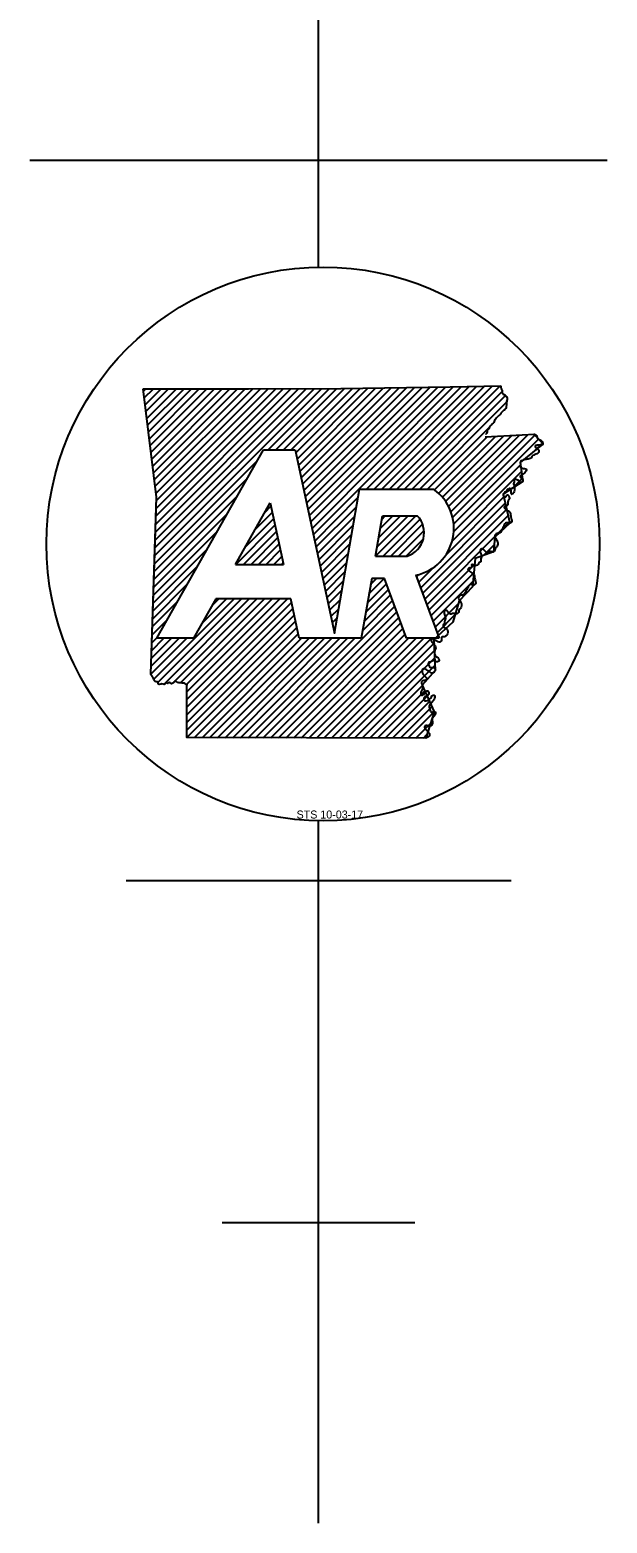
# Model space of a CAD drawing. Extents: x -13171 to 18763, y -8840 to 11152.
# Drawn here: x 5297 to 5823, y -4773 to -3413 of the extents above; entities that cross this region are included whole.
import ezdxf

# ---------------------------------------------------------------- set-up
doc = ezdxf.new("R2010")
doc.units = 0
doc.layers.add('Level 48', color=7, linetype='Continuous')

msp = doc.modelspace()

# ---------------------------------------------------------------- linework, layer by layer
at = {"layer": 'Level 48'}
for p, q in [((5560.1, -3629.5), (5560.1, -2053.7)), ((5296.9, -3532.1), (5823.2, -3532.1)), ((5545.6, -3827.2), (5633.5, -3739.3)), ((5546.8, -3833), (5640.5, -3739.2)), ((5548, -3838.7), (5647.6, -3739.1)), ((5549.2, -3844.4), (5654.7, -3739)), ((5550.5, -3850.2), (5661.8, -3738.9)), ((5551.7, -3855.9), (5668.8, -3738.8)), ((5552.9, -3861.6), (5675.9, -3738.7)), ((5554.2, -3867.4), (5683, -3738.5)), ((5555.4, -3873.1), (5690.1, -3738.4)), ((5603.8, -3831.7), (5697.3, -3738.2)), ((5610.7, -3831.7), (5704.4, -3738)), ((5617.7, -3831.7), (5711.5, -3737.9)), ((5624.7, -3831.7), (5718.7, -3737.7)), ((5631.6, -3831.7), (5725.8, -3737.5)), ((5400.5, -3742.4), (5402.7, -3740.3)), ((5401.3, -3748.6), (5409.6, -3740.3)), ((5402, -3754.8), (5416.6, -3740.3)), ((5402.8, -3761), (5423.5, -3740.3)), ((5403.6, -3767.2), (5430.5, -3740.3)), ((5404.3, -3773.4), (5437.5, -3740.3)), ((5405.1, -3779.6), (5444.4, -3740.3)), ((5405.9, -3785.8), (5451.4, -3740.3)), ((5406.7, -3792), (5458.3, -3740.3)), ((5407.4, -3798.2), (5465.3, -3740.3)), ((5408.2, -3804.4), (5472.3, -3740.3)), ((5409, -3810.6), (5479.2, -3740.3)), ((5409.7, -3816.8), (5486.2, -3740.3)), ((5410.5, -3823), (5493.2, -3740.3)), ((5410.7, -3892.4), (5562.9, -3740.2)), ((5411, -3885.2), (5556, -3740.2)), ((5411.2, -3878), (5549, -3740.2)), ((5411.3, -3829.1), (5500.1, -3740.3)), ((5411.5, -3870.8), (5542, -3740.2)), ((5411.7, -3863.6), (5535, -3740.2)), ((5411.9, -3856.4), (5528, -3740.2)), ((5412.1, -3835.3), (5507.1, -3740.3)), ((5412.2, -3849.2), (5521.1, -3740.3)), ((5412.4, -3841.9), (5514.1, -3740.3)), ((5514.2, -3795.9), (5569.9, -3740.2)), ((5521.1, -3795.9), (5576.9, -3740.1)), ((5528.1, -3795.9), (5583.9, -3740.1)), ((5535.1, -3795.9), (5591, -3740)), ((5539.4, -3798.5), (5598.1, -3739.9)), ((5540.6, -3804.3), (5605.2, -3739.8)), ((5541.9, -3810), (5612.2, -3739.6)), ((5543.1, -3815.7), (5619.3, -3739.5)), ((5544.3, -3821.5), (5626.4, -3739.4)), ((5638.6, -3831.7), (5727.4, -3742.9)), ((5645.6, -3831.7), (5730.7, -3746.5)), ((5652.5, -3831.7), (5731.6, -3752.6)), ((5659.5, -3831.7), (5715.7, -3775.5)), ((5665.8, -3832.3), (5714.3, -3783.8)), ((5669.6, -3835.5), (5721.7, -3783.4)), ((5673, -3839.1), (5729, -3783.1)), ((5676, -3843), (5736.4, -3782.7)), ((5678.6, -3847.4), (5743.7, -3782.3)), ((5680.8, -3852.2), (5751.1, -3781.9)), ((5682.4, -3857.6), (5757.7, -3782.3)), ((5683.3, -3863.6), (5760.9, -3786)), ((5757.8, -3796), (5764.2, -3789.7)), ((5410.5, -3899.6), (5504.5, -3805.6)), ((5412.8, -3967.5), (5510, -3795.9)), ((5510, -3795.9), (5538.9, -3795.9)), ((5681.9, -3879), (5745.1, -3815.7)), ((5683.3, -3870.5), (5744.3, -3809.6)), ((5410.3, -3906.8), (5495.4, -3821.6)), ((5597.5, -3831.7), (5664.9, -3831.7)), ((5737.3, -3830.5), (5745.9, -3821.9)), ((5410, -3914), (5486.3, -3837.7)), ((5484.3, -3900.2), (5516.1, -3844)), ((5511.1, -3852.8), (5516.7, -3847.1)), ((5556.6, -3878.9), (5596.1, -3839.3)), ((5557.8, -3884.6), (5594.7, -3847.8)), ((5653.1, -3921.7), (5730.3, -3844.4)), ((5675.8, -3892), (5729, -3838.8)), ((5409.8, -3921.2), (5477.2, -3853.8)), ((5492.9, -3884.9), (5519.2, -3858.6)), ((5502, -3868.8), (5518, -3852.9)), ((5559.1, -3890.3), (5593.2, -3856.2)), ((5612.2, -3892.6), (5648.8, -3855.9)), ((5613.6, -3884.2), (5641.8, -3855.9)), ((5615, -3875.7), (5634.9, -3855.9)), ((5616.5, -3867.3), (5627.9, -3855.9)), ((5618, -3858.9), (5620.9, -3855.9)), ((5618.5, -3855.9), (5650.2, -3855.9)), ((5619.1, -3892.6), (5652.7, -3859)), ((5655, -3926.7), (5731.6, -3850.1)), ((5656.9, -3931.8), (5733, -3855.8)), ((5658.8, -3936.9), (5734.3, -3861.4)), ((5409.5, -3928.4), (5468.1, -3869.8)), ((5484.6, -3900.2), (5520.4, -3864.4)), ((5491.6, -3900.2), (5521.7, -3870.1)), ((5560.3, -3896.1), (5591.7, -3864.6)), ((5561.5, -3901.8), (5590.3, -3873.1)), ((5626.1, -3892.6), (5655, -3863.6)), ((5633.1, -3892.6), (5656.3, -3869.3)), ((5409.3, -3935.6), (5459, -3885.9)), ((5498.6, -3900.2), (5522.9, -3875.8)), ((5505.5, -3900.2), (5524.1, -3881.6)), ((5512.5, -3900.2), (5525.3, -3887.3)), ((5562.7, -3907.5), (5588.8, -3881.5)), ((5640, -3892.6), (5655.7, -3876.9)), ((5710.4, -3892.2), (5720.2, -3882.4)), ((5409.1, -3942.8), (5449.9, -3901.9)), ((5484.3, -3900.2), (5528.1, -3900.2)), ((5519.5, -3900.2), (5526.6, -3893)), ((5526.4, -3900.2), (5527.8, -3898.8)), ((5564, -3913.3), (5587.3, -3889.9)), ((5565.2, -3919), (5585.8, -3898.4)), ((5612.1, -3892.6), (5641.1, -3892.6)), ((5660.6, -3942), (5702.4, -3900.2)), ((5566.4, -3924.8), (5584.4, -3906.8)), ((5567.7, -3930.5), (5582.9, -3915.3)), ((5606.1, -3926.9), (5620.1, -3912.9)), ((5607.6, -3918.4), (5613.1, -3912.9)), ((5620.3, -3912.9), (5608.6, -3912.9)), ((5640.4, -3967.5), (5620.3, -3912.9)), ((5648.8, -3910), (5670.1, -3967.5)), ((5649.4, -3911.5), (5651.5, -3909.4)), ((5651.2, -3916.6), (5664.5, -3903.3)), ((5662.5, -3947.1), (5701.6, -3908)), ((5664.4, -3952.2), (5700.9, -3915.7)), ((5408.8, -3950), (5440.8, -3918)), ((5568.9, -3936.2), (5581.4, -3923.7)), ((5601.7, -3952.2), (5625.8, -3928)), ((5603.2, -3943.7), (5624, -3923)), ((5604.7, -3935.3), (5622.1, -3917.9)), ((5408.6, -3957.2), (5431.7, -3934.1)), ((5409.9, -4004.7), (5483.1, -3931.5)), ((5414, -4007.5), (5490, -3931.5)), ((5419, -4009.5), (5497, -3931.5)), ((5427.3, -4008.2), (5504, -3931.5)), ((5434.4, -4008.1), (5510.9, -3931.5)), ((5439.8, -4009.6), (5517.9, -3931.5)), ((5440, -4016.3), (5524.9, -3931.5)), ((5440.1, -4023.3), (5531.8, -3931.5)), ((5440.1, -4030.2), (5535.5, -3934.8)), ((5440.1, -4037.2), (5536.7, -3940.5)), ((5466.5, -3931.5), (5446.2, -3967.5)), ((5454.1, -3953.6), (5476.1, -3931.5)), ((5463.1, -3937.5), (5469.1, -3931.5)), ((5534.8, -3931.5), (5466.5, -3931.5)), ((5509.8, -4058), (5629.6, -3938.2)), ((5516.7, -4058), (5631.5, -3943.3)), ((5570.1, -3942), (5580, -3932.1)), ((5571.3, -3947.7), (5578.5, -3940.6)), ((5600.3, -3960.6), (5627.7, -3933.1)), ((5666.3, -3957.3), (5687.6, -3935.9)), ((5408.4, -3964.4), (5422.7, -3950.1)), ((5440.1, -4044.1), (5538, -3946.3)), ((5440.1, -4051.1), (5539.2, -3952)), ((5523.7, -4058), (5633.4, -3948.4)), ((5530.7, -4058.1), (5635.2, -3953.5)), ((5572.6, -3953.5), (5577, -3949)), ((5668.2, -3962.4), (5684.7, -3945.9)), ((5407.3, -4000.3), (5440.1, -3967.5)), ((5407.4, -3993.2), (5433.1, -3967.5)), ((5407.6, -3986), (5426.2, -3967.5)), ((5407.9, -3978.8), (5419.2, -3967.5)), ((5408.1, -3971.6), (5413.6, -3966.2)), ((5446.2, -3967.5), (5412.8, -3967.5)), ((5440.2, -4057.9), (5540.4, -3957.7)), ((5447.2, -4057.9), (5541.6, -3963.5)), ((5454.2, -4057.9), (5544.6, -3967.5)), ((5461.1, -4057.9), (5551.6, -3967.5)), ((5468.1, -4058), (5558.5, -3967.5)), ((5475, -4058), (5565.5, -3967.5)), ((5482, -4058), (5572.4, -3967.5)), ((5488.9, -4058), (5579.4, -3967.5)), ((5495.9, -4058), (5586.4, -3967.5)), ((5502.8, -4058), (5593.3, -3967.5)), ((5537.6, -4058.1), (5637.1, -3958.6)), ((5599.1, -3967.5), (5542.5, -3967.5)), ((5544.6, -4058.1), (5639, -3963.7)), ((5551.5, -4058.1), (5642.1, -3967.5)), ((5558.5, -4058.1), (5649.1, -3967.5)), ((5565.4, -4058.1), (5656, -3967.5)), ((5572.4, -4058.1), (5663, -3967.5)), ((5573.8, -3959.2), (5575.6, -3957.4)), ((5670.1, -3967.5), (5640.4, -3967.5)), ((5579.3, -4058.1), (5665.3, -3972.1)), ((5586.3, -4058.1), (5665.6, -3978.8)), ((5593.2, -4058.2), (5666, -3985.4)), ((5600.2, -4058.2), (5666.3, -3992.1)), ((5607.2, -4058.2), (5654.8, -4010.5)), ((5614.1, -4058.2), (5657, -4015.3)), ((5621.1, -4058.2), (5659.1, -4020.1)), ((5628, -4058.2), (5661.3, -4025)), ((5635, -4058.2), (5663.4, -4029.8)), ((5641.9, -4058.2), (5665.2, -4034.9)), ((5648.9, -4058.3), (5662.1, -4045.1)), ((5655.8, -4058.3), (5658.9, -4055.2)), ((5560.1, -4773.2), (5560.1, -4133.6)), ((5384.7, -4188), (5735.6, -4188)), ((5472.4, -4499.6), (5647.8, -4499.6))]:
    msp.add_line(p, q, dxfattribs=at)
for points in [[(5400.2, -3740.3), (5496.3, -3740.3), (5580.7, -3740.1), (5680.1, -3738.6), (5726.2, -3737.5)], [(5400.2, -3740.3), (5496.3, -3740.3), (5580.6, -3740.1), (5680.1, -3738.6), (5726.2, -3737.5)], [(5410.8, -3889.7), (5412.5, -3839), (5400.2, -3740.3)], [(5407.2, -4000.3), (5412.5, -3839), (5400.2, -3740.3)], [(5756.4, -3781.7), (5764.8, -3790.4), (5744, -3807.4), (5746.3, -3824.6), (5728.5, -3836.3), (5734.6, -3862.8), (5720.9, -3875.3), (5719.6, -3888.9), (5703, -3894.9), (5700.4, -3920.5), (5688.4, -3933.4), (5682.6, -3952.7), (5665.2, -3968.6), (5666.5, -3996.8), (5654.6, -4010.1), (5665.4, -4034.3), (5658, -4058.3)], [(5712, -3783.9), (5757.1, -3781.6)], [(5712, -3783.9), (5757.1, -3781.6)], [(5538.9, -3795.9), (5574.6, -3962.9), (5597.5, -3831.7)], [(5516.1, -3844), (5528.1, -3900.2)], [(5612.1, -3892.6), (5618.5, -3855.9)], [(5407.2, -4000.3), (5410.8, -3889.7)], [(5608.6, -3912.9), (5599.1, -3967.5)], [(5542.5, -3967.5), (5534.8, -3931.5)], [(5658, -4058.3), (5440.1, -4057.9), (5440, -4009.8)], [(5657.9, -4058.3), (5440.1, -4057.9), (5440.1, -4009.8)]]:
    msp.add_lwpolyline(points, dxfattribs=at)
msp.add_ellipse((5564.2, -3881.6), major_axis=(252.1, 0), ratio=0.999976, dxfattribs=at)
for centre, major_axis, start_param, end_param in [((5639.9, -3867.4), (-43.6, 0), 1.777838, 4.099264), ((5634.1, -3871.4), (-22.3, 0), 1.887169, 3.90762)]:
    msp.add_ellipse(centre, major_axis=major_axis, ratio=0.999987, start_param=start_param, end_param=end_param, dxfattribs=at)
for points in [[(5726.2, -3737.5), (5726.5, -3740.1), (5727.3, -3741.5), (5727.5, -3744), (5728.5, -3745.1), (5730.3, -3746.2), (5731.7, -3747.8), (5732.1, -3749.9), (5731.6, -3751.9), (5731.5, -3754.3), (5731.3, -3756.3), (5730.9, -3758.1), (5729.5, -3759.6), (5728.2, -3760.7), (5726.9, -3761.9), (5726, -3763.3), (5724.5, -3764.7), (5722.9, -3766.2), (5721.6, -3767.5), (5720.4, -3769.1), (5719.8, -3771), (5718.5, -3772.3), (5717.4, -3773.5), (5716, -3775.1), (5715.3, -3776.7), (5713.9, -3778.5), (5713.6, -3780.3), (5712.7, -3781.7), (5712.6, -3782)], [(5726.2, -3737.5), (5726.5, -3740.1), (5727.4, -3741.5), (5727.5, -3744), (5728.5, -3745.1), (5730.2, -3746.1), (5731.8, -3747.9), (5732.1, -3749.9), (5731.7, -3752), (5731.5, -3754.3), (5731.3, -3756.3), (5730.9, -3758.1), (5729.5, -3759.6), (5728.1, -3760.7), (5726.9, -3761.9), (5726, -3763.3), (5724.5, -3764.7), (5722.9, -3766.2), (5721.7, -3767.5), (5720.4, -3769.1), (5719.8, -3771), (5718.5, -3772.3), (5717.4, -3773.5), (5716, -3775.1), (5715.3, -3776.7), (5713.9, -3778.5), (5713.6, -3780.3), (5712.7, -3781.7), (5712.6, -3782)], [(5756.4, -3781.7), (5757.1, -3781.6), (5759.1, -3783.7), (5760, -3785.6), (5761.3, -3786.5), (5762.8, -3787.1), (5763.9, -3788.4), (5764.7, -3790), (5764.3, -3791.3), (5762.6, -3791.4), (5760.8, -3791.7), (5759, -3791.6), (5757.5, -3792.8), (5758.9, -3794.4), (5760.6, -3795.9), (5761.1, -3797.5), (5760.1, -3799), (5758.2, -3799.9), (5756.4, -3800.6), (5754.7, -3802), (5753.9, -3803.4), (5752.1, -3804), (5750.2, -3804.5), (5748.5, -3804.7), (5746.6, -3805.1), (5744.8, -3806), (5744, -3807.5), (5744.3, -3809.7), (5744.2, -3812), (5746.1, -3812.7), (5747.9, -3812.8), (5749.6, -3813.7), (5749.4, -3815), (5748.1, -3816.7), (5746.6, -3818), (5745.2, -3818.6), (5743.8, -3819.9), (5744.3, -3821.2), (5745.5, -3821.9), (5746.4, -3823.3), (5746.3, -3824.6), (5744.8, -3825.5), (5743.3, -3825.1), (5742.1, -3823.6), (5740.9, -3823.2), (5739.7, -3822.6), (5738.4, -3823.4), (5738.4, -3825.1), (5738, -3826.9), (5738.4, -3828.3), (5738.9, -3830.2), (5738.8, -3831.6), (5738.4, -3833.7), (5737.3, -3835.8), (5736.2, -3836.4), (5735.6, -3834.2), (5735.5, -3832.3), (5734.7, -3831.2), (5733.8, -3831.2), (5732.5, -3832.1), (5731.2, -3833.5), (5729.5, -3834.9), (5728.4, -3836.4), (5729, -3838.2), (5730.3, -3838.7), (5731.3, -3838.4), (5731.8, -3837.2), (5732.8, -3837), (5733.8, -3838.9)], [(5733.8, -3838.9), (5734.1, -3840.6), (5733, -3842.4), (5732.6, -3844.2), (5732.8, -3846.1), (5730.9, -3847.1), (5729.3, -3848.3), (5730.3, -3849.7), (5732.1, -3851), (5733.8, -3852), (5734.9, -3853.1), (5735.2, -3855.5), (5735.5, -3857), (5736.1, -3859.2), (5736.3, -3860.7), (5735.3, -3862.4), (5734.1, -3862.8), (5732.7, -3862.4), (5731.2, -3862.3), (5729.9, -3863.4), (5729, -3865.1), (5728.2, -3866.8), (5727.5, -3868.2), (5726.8, -3869.7), (5725.5, -3871.6), (5723.9, -3871.8), (5722, -3872.3), (5720.9, -3873.6), (5721.1, -3875.8), (5722.2, -3877.3), (5723, -3879.1), (5723.6, -3880.7), (5723.3, -3882.8), (5722.5, -3884.3), (5721.4, -3885.2), (5720.9, -3887), (5720.1, -3888.5), (5719.4, -3889), (5718, -3888.8), (5716.4, -3888.5), (5715.1, -3888.7), (5713.9, -3889.3), (5712.6, -3888.9), (5711.3, -3887.4), (5710.2, -3886.4), (5709, -3886), (5707.8, -3886.6), (5707.6, -3888.6), (5708.2, -3890.6), (5708.7, -3893.3), (5708.2, -3895), (5708, -3897.8)], [(5708, -3897.8), (5705.9, -3899.3), (5705, -3901), (5699.7, -3900.5), (5699.8, -3902.4), (5698, -3903.3), (5696.3, -3904.5), (5697.2, -3906), (5699, -3907.3), (5700.8, -3908.3), (5701.9, -3909.3), (5702.2, -3911.8), (5702.6, -3913.3), (5703.1, -3915.5), (5703.4, -3916.9), (5702.3, -3918.7), (5701, -3919), (5699.8, -3918.6), (5698.2, -3918.5), (5697, -3919.7), (5696.1, -3921.4), (5695.2, -3923), (5694.5, -3924.5), (5693.8, -3926), (5692.6, -3927.8), (5691, -3928.1), (5689.1, -3928.5), (5687.9, -3929.8), (5688.1, -3932.1), (5689.2, -3933.5), (5690, -3935.4), (5690.6, -3937), (5690.3, -3939), (5689.5, -3940.5), (5688.4, -3941.4), (5687.9, -3943.3), (5687.1, -3944.7), (5686.4, -3945.2), (5685, -3945), (5683.5, -3944.8), (5682.2, -3944.9), (5680.9, -3945.5), (5679.7, -3945.1), (5678.4, -3943.7), (5677.3, -3942.6), (5676.1, -3942.2), (5674.8, -3942.9), (5674.6, -3944.8), (5675.2, -3946.8), (5675.8, -3949.6), (5675.2, -3951.2), (5675.1, -3954)], [(5675.1, -3954), (5674.9, -3954.1), (5673.8, -3955.4), (5674.4, -3957.5), (5676.7, -3958.4), (5677.8, -3960.4), (5677.9, -3962.1), (5677.1, -3964.6), (5676, -3965.7), (5674, -3966.2), (5672.4, -3966.5), (5672.1, -3969.2), (5671.4, -3970.6), (5670.2, -3971), (5668.4, -3970.1), (5667.3, -3969.7), (5666, -3969.1), (5664.3, -3968.1), (5663, -3968.3), (5663.4, -3970.9), (5663.5, -3971), (5665, -3973), (5666.4, -3974.5), (5667, -3976.4)], [(5675.1, -3954), (5674.9, -3954.1), (5673.8, -3955.4), (5674.4, -3957.5), (5676.7, -3958.4), (5677.8, -3960.4), (5677.9, -3962.1), (5677.1, -3964.6), (5676, -3965.7), (5674, -3966.2), (5672.4, -3966.5), (5672.1, -3969.2), (5671.4, -3970.6), (5670.2, -3971), (5668.4, -3970.1), (5667.3, -3969.7), (5666, -3969.1), (5664.3, -3968.1), (5663, -3968.3), (5663.4, -3970.9), (5663.5, -3971), (5665, -3973), (5666.4, -3974.5), (5667, -3976.4)], [(5667, -3976.4), (5666.5, -3977.8), (5665.8, -3980.1), (5666, -3982.1), (5666.9, -3983.8), (5668.3, -3984.8), (5669.9, -3986.2), (5669.7, -3988.3), (5668.8, -3989), (5666.7, -3988.5), (5665.1, -3987.8), (5663.8, -3988.2), (5662, -3989.1), (5660.6, -3989.3), (5660.6, -3992.1), (5662.5, -3994.1), (5664.1, -3994.1), (5665.9, -3994.4), (5666.6, -3996.5), (5665.5, -3998.3), (5663.7, -3999.2), (5661.5, -3998.1), (5659.9, -3997), (5658.3, -3995.9), (5656.3, -3995.4), (5655.1, -3995.6), (5654.6, -3998.1), (5655.5, -4000.4), (5657, -4001.9), (5658.5, -4003.9), (5658.3, -4005.5), (5657.2, -4005.8), (5655.3, -4006.3), (5654.2, -4006.8), (5653.9, -4007.3), (5654.5, -4009.4), (5655, -4011.5), (5655, -4013.2), (5654.3, -4014.7), (5653.3, -4017.1), (5653.4, -4018.6), (5654.2, -4019.4), (5655, -4019.2), (5656.3, -4018.3), (5657, -4017.4), (5657.7, -4016.2), (5658.9, -4015.2), (5660.4, -4016.1), (5660.8, -4017.9), (5659.9, -4019.5), (5658.7, -4020.3), (5657.1, -4020.8), (5656, -4022.1), (5656.3, -4023.7), (5657.2, -4024.5), (5659.4, -4024.1), (5660.9, -4023.4), (5661.7, -4022.6), (5662.7, -4021.6), (5663.2, -4020.6), (5664, -4019.5), (5665.4, -4019.2), (5666.1, -4020.1), (5665.8, -4022.1), (5665, -4024.1), (5663.8, -4025.6), (5662.6, -4026.7), (5661, -4029.2), (5661.4, -4031.4), (5662, -4033.3), (5662.7, -4034.7), (5664.2, -4034.4), (5665.8, -4034.3), (5666.7, -4035), (5666.6, -4036.7), (5665.5, -4038.3), (5664.3, -4039.9), (5663.7, -4042), (5664, -4043.5), (5664, -4044.8), (5663.5, -4046.3), (5662.7, -4047.2), (5660.4, -4047.1), (5658.1, -4046.9), (5656.9, -4047.6), (5657.1, -4049.6), (5658.5, -4051.1), (5659.4, -4051.8), (5660.8, -4053.5), (5661.4, -4054.9), (5661.2, -4056.1), (5660.4, -4057.1), (5657.9, -4058.3)], [(5667, -3976.4), (5666.5, -3977.8), (5665.8, -3980.1), (5666, -3982.1), (5666.9, -3983.8), (5668.3, -3984.8), (5669.9, -3986.2), (5669.7, -3988.3), (5668.8, -3989), (5666.7, -3988.5), (5665.1, -3987.8), (5663.8, -3988.2), (5662, -3989.1), (5660.6, -3989.3), (5660.6, -3992.1), (5662.5, -3994.1), (5664.1, -3994.1), (5665.9, -3994.4), (5666.6, -3996.5), (5665.5, -3998.3), (5663.7, -3999.2), (5661.5, -3998.1), (5659.9, -3997), (5658.3, -3995.9), (5656.3, -3995.4), (5655.1, -3995.6), (5654.6, -3998.1), (5655.5, -4000.4), (5657, -4001.9), (5658.5, -4003.9), (5658.3, -4005.5), (5657.2, -4005.8), (5655.3, -4006.3), (5654.2, -4006.8), (5653.9, -4007.3), (5654.5, -4009.4), (5655, -4011.5), (5655, -4013.2), (5654.3, -4014.7), (5653.3, -4017.1), (5653.4, -4018.6), (5654.2, -4019.4), (5655, -4019.2), (5656.3, -4018.3), (5657, -4017.4), (5657.7, -4016.2), (5658.9, -4015.2), (5660.4, -4016.1), (5660.8, -4017.9), (5659.9, -4019.5), (5658.7, -4020.3), (5657.1, -4020.8), (5656, -4022.1), (5656.3, -4023.7), (5657.2, -4024.5), (5659.4, -4024.1), (5660.9, -4023.4), (5661.7, -4022.6), (5662.7, -4021.6), (5663.2, -4020.6), (5664, -4019.5), (5665.4, -4019.2), (5666.1, -4020.1), (5665.8, -4022.1), (5665, -4024.1), (5663.8, -4025.6), (5662.6, -4026.7), (5661, -4029.2), (5661.4, -4031.4), (5662, -4033.3), (5662.7, -4034.7), (5664.2, -4034.4), (5665.8, -4034.3), (5666.7, -4035), (5666.6, -4036.7), (5665.5, -4038.3), (5664.3, -4039.9), (5663.7, -4042), (5664, -4043.5), (5664, -4044.8), (5663.5, -4046.3), (5662.7, -4047.2), (5660.4, -4047.1), (5658.1, -4046.9), (5656.9, -4047.6), (5657.1, -4049.6), (5658.5, -4051.1), (5659.4, -4051.8), (5660.8, -4053.5), (5661.4, -4054.9), (5661.2, -4056.1), (5660.4, -4057.1), (5657.9, -4058.3)], [(5440.1, -4009.8), (5440.3, -4009.9), (5439.2, -4009.2), (5437.6, -4008.4), (5435.8, -4008.3), (5433.6, -4008), (5431.8, -4007.8), (5429.9, -4006.6), (5427.9, -4007.8), (5425.7, -4008.8), (5424.3, -4007.7), (5422.6, -4008.5), (5421.4, -4008.1), (5419.4, -4009.5), (5417.4, -4009), (5416, -4009.4), (5414.2, -4009.4), (5413.8, -4007.3), (5412.1, -4007.1), (5410.6, -4006.2), (5409.6, -4004.1), (5408.9, -4002.5), (5407.2, -4000.3)], [(5440, -4009.8), (5440.3, -4010), (5439.1, -4009.2), (5437.6, -4008.4), (5435.9, -4008.3), (5433.7, -4008), (5431.8, -4007.8), (5429.9, -4006.6), (5427.9, -4007.9), (5425.6, -4008.8), (5424.3, -4007.8), (5422.6, -4008.5), (5421.4, -4008.1), (5419.3, -4009.5), (5417.4, -4009), (5416, -4009.4), (5414.2, -4009.4), (5413.8, -4007.3), (5412.1, -4007), (5410.6, -4006.2), (5409.6, -4004.1), (5408.9, -4002.5), (5407.2, -4000.3)]]:
    msp.add_spline(points, degree=3, dxfattribs=at)

# ---------------------------------------------------------------- texts
msp.add_text('STS 10-03-17', height=7.288, dxfattribs=at).set_placement((5540.1, -4131.6))

doc.saveas('drawing.dxf')
